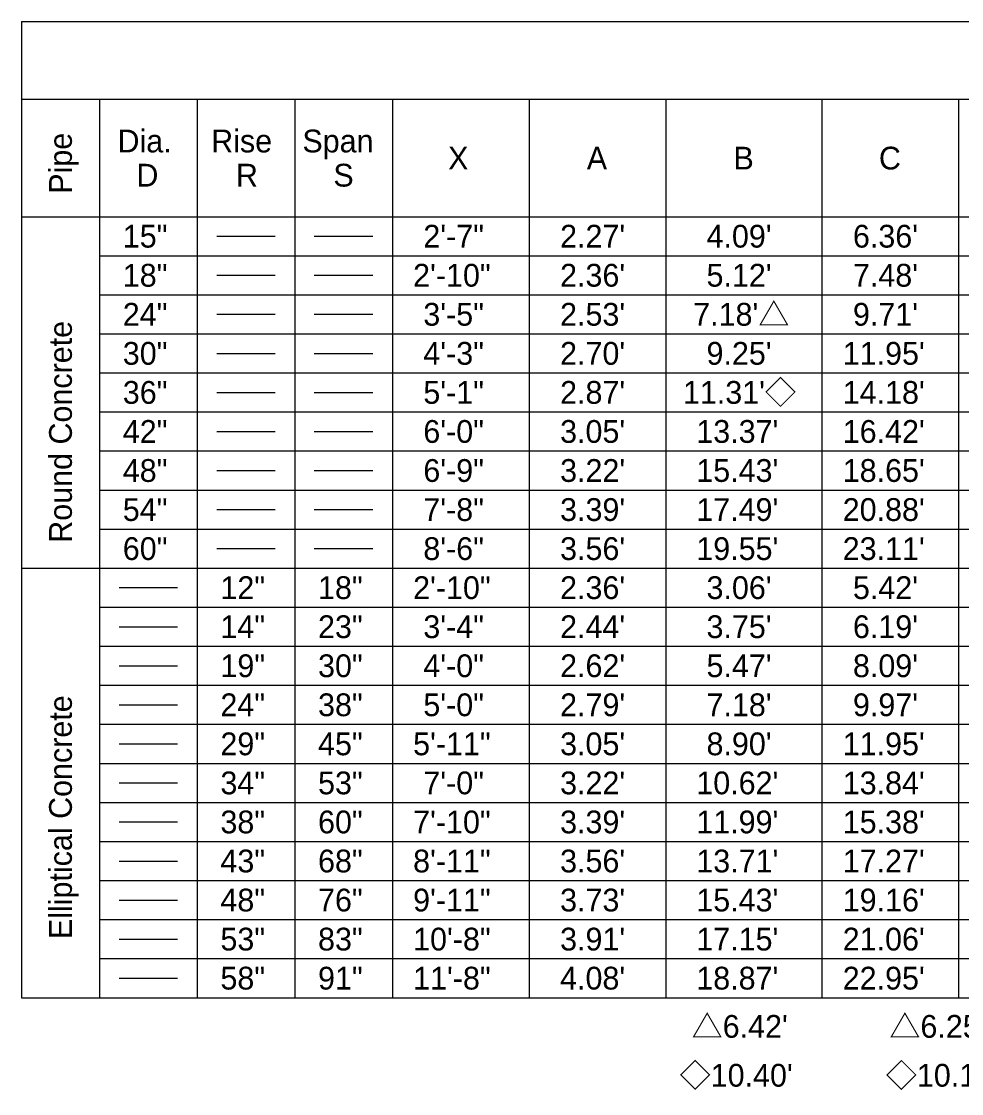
# Model space of a CAD drawing. Extents: x 2 to 14.5, y 0.1 to 8.2.
# Drawn here: x 2 to 4.889, y 4.933 to 8.227 of the extents above; entities that cross this region are included whole.
import ezdxf

# ---------------------------------------------------------------- set-up
doc = ezdxf.new("R2010")
doc.units = 0
doc.layers.add('TextNotes', color=7, linetype='Continuous')
doc.layers.add('TextTables', color=7, linetype='Continuous')

msp = doc.modelspace()

# ---------------------------------------------------------------- linework, layer by layer
at = {"layer": 'TextTables'}
for p, q in [((2, 8.2274), (13.4, 8.2274)), ((2.6, 7.5674), (2.78, 7.5674)), ((2.9, 7.5674), (3.08, 7.5674)), ((2.6, 7.4474), (2.78, 7.4474)), ((2.9, 7.4474), (3.08, 7.4474)), ((2.6, 7.3274), (2.78, 7.3274)), ((2.9, 7.3274), (3.08, 7.3274)), ((2.6, 7.2074), (2.78, 7.2074)), ((2.9, 7.2074), (3.08, 7.2074)), ((2.6, 7.0874), (2.78, 7.0874)), ((2.9, 7.0874), (3.08, 7.0874)), ((2.6, 6.9674), (2.78, 6.9674)), ((2.9, 6.9674), (3.08, 6.9674)), ((2.6, 6.8474), (2.78, 6.8474)), ((2.9, 6.8474), (3.08, 6.8474)), ((2.6, 6.7274), (2.78, 6.7274)), ((2.9, 6.7274), (3.08, 6.7274)), ((2.6, 6.6074), (2.78, 6.6074)), ((2.9, 6.6074), (3.08, 6.6074)), ((2.3, 6.4874), (2.48, 6.4874)), ((2.3, 6.3674), (2.48, 6.3674)), ((2.3, 6.2474), (2.48, 6.2474)), ((2.3, 6.1274), (2.48, 6.1274)), ((2.3, 6.0074), (2.48, 6.0074)), ((2.3, 5.8874), (2.48, 5.8874)), ((2.3, 5.7674), (2.48, 5.7674)), ((2.3, 5.6474), (2.48, 5.6474)), ((2.3, 5.5274), (2.48, 5.5274)), ((2.3, 5.4074), (2.48, 5.4074)), ((2.3, 5.2874), (2.48, 5.2874))]:
    msp.add_line(p, q, dxfattribs=at)
for points in [[(2, 8.2274), (2, 7.9874), (2, 7.6274), (2, 6.5474), (2, 5.2274)], [(13.4, 7.9874), (11.72, 7.9874), (10.04, 7.9874), (8.36, 7.9874), (8, 7.9874), (6.32, 7.9874), (5.96, 7.9874), (5.6, 7.9874), (5.36, 7.9874), (4.88, 7.9874), (4.46, 7.9874), (3.98, 7.9874), (3.56, 7.9874), (3.14, 7.9874), (2.84, 7.9874), (2.54, 7.9874), (2.24, 7.9874), (2, 7.9874)], [(2.24, 7.9874), (2.24, 7.6274), (2.24, 7.5074), (2.24, 7.3874), (2.24, 7.2674), (2.24, 7.1474), (2.24, 7.0274), (2.24, 6.9074), (2.24, 6.7874), (2.24, 6.6674), (2.24, 6.5474), (2.24, 6.4274), (2.24, 6.3074), (2.24, 6.1874), (2.24, 6.0674), (2.24, 5.9474), (2.24, 5.8274), (2.24, 5.7074), (2.24, 5.5874), (2.24, 5.4674), (2.24, 5.3474), (2.24, 5.2274)], [(2.54, 7.9874), (2.54, 7.6274), (2.54, 7.5074), (2.54, 7.3874), (2.54, 7.2674), (2.54, 7.1474), (2.54, 7.0274), (2.54, 6.9074), (2.54, 6.7874), (2.54, 6.6674), (2.54, 6.5474), (2.54, 6.4274), (2.54, 6.3074), (2.54, 6.1874), (2.54, 6.0674), (2.54, 5.9474), (2.54, 5.8274), (2.54, 5.7074), (2.54, 5.5874), (2.54, 5.4674), (2.54, 5.3474), (2.54, 5.2274)], [(2.84, 7.9874), (2.84, 7.6274), (2.84, 7.5074), (2.84, 7.3874), (2.84, 7.2674), (2.84, 7.1474), (2.84, 7.0274), (2.84, 6.9074), (2.84, 6.7874), (2.84, 6.6674), (2.84, 6.5474), (2.84, 6.4274), (2.84, 6.3074), (2.84, 6.1874), (2.84, 6.0674), (2.84, 5.9474), (2.84, 5.8274), (2.84, 5.7074), (2.84, 5.5874), (2.84, 5.4674), (2.84, 5.3474), (2.84, 5.2274)], [(3.14, 7.9874), (3.14, 7.6274), (3.14, 7.5074), (3.14, 7.3874), (3.14, 7.2674), (3.14, 7.1474), (3.14, 7.0274), (3.14, 6.9074), (3.14, 6.7874), (3.14, 6.6674), (3.14, 6.5474), (3.14, 6.4274), (3.14, 6.3074), (3.14, 6.1874), (3.14, 6.0674), (3.14, 5.9474), (3.14, 5.8274), (3.14, 5.7074), (3.14, 5.5874), (3.14, 5.4674), (3.14, 5.3474), (3.14, 5.2274)], [(3.56, 7.9874), (3.56, 7.6274), (3.56, 7.5074), (3.56, 7.3874), (3.56, 7.2674), (3.56, 7.1474), (3.56, 7.0274), (3.56, 6.9074), (3.56, 6.7874), (3.56, 6.6674), (3.56, 6.5474), (3.56, 6.4274), (3.56, 6.3074), (3.56, 6.1874), (3.56, 6.0674), (3.56, 5.9474), (3.56, 5.8274), (3.56, 5.7074), (3.56, 5.5874), (3.56, 5.4674), (3.56, 5.3474), (3.56, 5.2274)], [(3.98, 7.9874), (3.98, 7.6274), (3.98, 7.5074), (3.98, 7.3874), (3.98, 7.2674), (3.98, 7.1474), (3.98, 7.0274), (3.98, 6.9074), (3.98, 6.7874), (3.98, 6.6674), (3.98, 6.5474), (3.98, 6.4274), (3.98, 6.3074), (3.98, 6.1874), (3.98, 6.0674), (3.98, 5.9474), (3.98, 5.8274), (3.98, 5.7074), (3.98, 5.5874), (3.98, 5.4674), (3.98, 5.3474), (3.98, 5.2274)], [(4.46, 7.9874), (4.46, 7.6274), (4.46, 7.5074), (4.46, 7.3874), (4.46, 7.2674), (4.46, 7.1474), (4.46, 7.0274), (4.46, 6.9074), (4.46, 6.7874), (4.46, 6.6674), (4.46, 6.5474), (4.46, 6.4274), (4.46, 6.3074), (4.46, 6.1874), (4.46, 6.0674), (4.46, 5.9474), (4.46, 5.8274), (4.46, 5.7074), (4.46, 5.5874), (4.46, 5.4674), (4.46, 5.3474), (4.46, 5.2274)], [(4.88, 7.9874), (4.88, 7.6274), (4.88, 7.5074), (4.88, 7.3874), (4.88, 7.2674), (4.88, 7.1474), (4.88, 7.0274), (4.88, 6.9074), (4.88, 6.7874), (4.88, 6.6674), (4.88, 6.5474), (4.88, 6.4274), (4.88, 6.3074), (4.88, 6.1874), (4.88, 6.0674), (4.88, 5.9474), (4.88, 5.8274), (4.88, 5.7074), (4.88, 5.5874), (4.88, 5.4674), (4.88, 5.3474), (4.88, 5.2274)], [(2, 7.6274), (2.24, 7.6274), (2.54, 7.6274), (2.84, 7.6274), (3.14, 7.6274), (3.56, 7.6274), (3.98, 7.6274), (4.46, 7.6274), (4.88, 7.6274), (5.36, 7.6274), (5.6, 7.6274), (5.96, 7.6274), (6.32, 7.6274), (6.74, 7.6274), (7.16, 7.6274), (7.58, 7.6274), (8, 7.6274), (8.36, 7.6274)], [(2.24, 7.5074), (2.54, 7.5074), (2.84, 7.5074), (3.14, 7.5074), (3.56, 7.5074), (3.98, 7.5074), (4.46, 7.5074), (4.88, 7.5074), (5.36, 7.5074), (5.6, 7.5074), (5.96, 7.5074), (6.32, 7.5074), (6.74, 7.5074), (7.16, 7.5074), (7.58, 7.5074), (8, 7.5074), (8.36, 7.5074)], [(2.24, 7.3874), (2.54, 7.3874), (2.84, 7.3874), (3.14, 7.3874), (3.56, 7.3874), (3.98, 7.3874), (4.46, 7.3874), (4.88, 7.3874), (5.36, 7.3874), (5.6, 7.3874), (5.96, 7.3874), (6.32, 7.3874), (6.74, 7.3874), (7.16, 7.3874), (7.58, 7.3874), (8, 7.3874), (8.36, 7.3874)], [(2.24, 7.2674), (2.54, 7.2674), (2.84, 7.2674), (3.14, 7.2674), (3.56, 7.2674), (3.98, 7.2674), (4.46, 7.2674), (4.88, 7.2674), (5.36, 7.2674), (5.6, 7.2674), (5.96, 7.2674), (6.32, 7.2674), (6.74, 7.2674), (7.16, 7.2674), (7.58, 7.2674), (8, 7.2674), (8.36, 7.2674)], [(2.24, 7.1474), (2.54, 7.1474), (2.84, 7.1474), (3.14, 7.1474), (3.56, 7.1474), (3.98, 7.1474), (4.46, 7.1474), (4.88, 7.1474), (5.36, 7.1474), (5.6, 7.1474), (5.96, 7.1474), (6.32, 7.1474), (6.74, 7.1474), (7.16, 7.1474), (7.58, 7.1474), (8, 7.1474), (8.36, 7.1474)], [(2.24, 7.0274), (2.54, 7.0274), (2.84, 7.0274), (3.14, 7.0274), (3.56, 7.0274), (3.98, 7.0274), (4.46, 7.0274), (4.88, 7.0274), (5.36, 7.0274), (5.6, 7.0274), (5.96, 7.0274), (6.32, 7.0274), (6.74, 7.0274), (7.16, 7.0274), (7.58, 7.0274), (8, 7.0274), (8.36, 7.0274)], [(2.24, 6.9074), (2.54, 6.9074), (2.84, 6.9074), (3.14, 6.9074), (3.56, 6.9074), (3.98, 6.9074), (4.46, 6.9074), (4.88, 6.9074), (5.36, 6.9074), (5.6, 6.9074), (5.96, 6.9074), (6.32, 6.9074), (6.74, 6.9074), (7.16, 6.9074), (7.58, 6.9074), (8, 6.9074), (8.36, 6.9074)], [(2.24, 6.7874), (2.54, 6.7874), (2.84, 6.7874), (3.14, 6.7874), (3.56, 6.7874), (3.98, 6.7874), (4.46, 6.7874), (4.88, 6.7874), (5.36, 6.7874), (5.6, 6.7874), (5.96, 6.7874), (6.32, 6.7874), (6.74, 6.7874), (7.16, 6.7874), (7.58, 6.7874), (8, 6.7874), (8.36, 6.7874)], [(2.24, 6.6674), (2.54, 6.6674), (2.84, 6.6674), (3.14, 6.6674), (3.56, 6.6674), (3.98, 6.6674), (4.46, 6.6674), (4.88, 6.6674), (5.36, 6.6674), (5.6, 6.6674), (5.96, 6.6674), (6.32, 6.6674), (6.74, 6.6674), (7.16, 6.6674), (7.58, 6.6674), (8, 6.6674), (8.36, 6.6674)], [(2, 6.5474), (2.24, 6.5474), (2.54, 6.5474), (2.84, 6.5474), (3.14, 6.5474), (3.56, 6.5474), (3.98, 6.5474), (4.46, 6.5474), (4.88, 6.5474), (5.36, 6.5474), (5.6, 6.5474), (5.96, 6.5474), (6.32, 6.5474), (6.74, 6.5474), (7.16, 6.5474), (7.58, 6.5474), (8, 6.5474), (8.36, 6.5474)], [(2.24, 6.4274), (2.54, 6.4274), (2.84, 6.4274), (3.14, 6.4274), (3.56, 6.4274), (3.98, 6.4274), (4.46, 6.4274), (4.88, 6.4274), (5.36, 6.4274), (5.6, 6.4274), (5.96, 6.4274), (6.32, 6.4274), (6.74, 6.4274), (7.16, 6.4274), (7.58, 6.4274), (8, 6.4274), (8.36, 6.4274)], [(2.24, 6.3074), (2.54, 6.3074), (2.84, 6.3074), (3.14, 6.3074), (3.56, 6.3074), (3.98, 6.3074), (4.46, 6.3074), (4.88, 6.3074), (5.36, 6.3074), (5.6, 6.3074), (5.96, 6.3074), (6.32, 6.3074), (6.74, 6.3074), (7.16, 6.3074), (7.58, 6.3074), (8, 6.3074), (8.36, 6.3074)], [(2.24, 6.1874), (2.54, 6.1874), (2.84, 6.1874), (3.14, 6.1874), (3.56, 6.1874), (3.98, 6.1874), (4.46, 6.1874), (4.88, 6.1874), (5.36, 6.1874), (5.6, 6.1874), (5.96, 6.1874), (6.32, 6.1874), (6.74, 6.1874), (7.16, 6.1874), (7.58, 6.1874), (8, 6.1874), (8.36, 6.1874)], [(2.24, 6.0674), (2.54, 6.0674), (2.84, 6.0674), (3.14, 6.0674), (3.56, 6.0674), (3.98, 6.0674), (4.46, 6.0674), (4.88, 6.0674), (5.36, 6.0674), (5.6, 6.0674), (5.96, 6.0674), (6.32, 6.0674), (6.74, 6.0674), (7.16, 6.0674), (7.58, 6.0674), (8, 6.0674), (8.36, 6.0674)], [(2.24, 5.9474), (2.54, 5.9474), (2.84, 5.9474), (3.14, 5.9474), (3.56, 5.9474), (3.98, 5.9474), (4.46, 5.9474), (4.88, 5.9474), (5.36, 5.9474), (5.6, 5.9474), (5.96, 5.9474), (6.32, 5.9474), (6.74, 5.9474), (7.16, 5.9474), (7.58, 5.9474), (8, 5.9474), (8.36, 5.9474)], [(2.24, 5.8274), (2.54, 5.8274), (2.84, 5.8274), (3.14, 5.8274), (3.56, 5.8274), (3.98, 5.8274), (4.46, 5.8274), (4.88, 5.8274), (5.36, 5.8274), (5.6, 5.8274), (5.96, 5.8274), (6.32, 5.8274), (6.74, 5.8274), (7.16, 5.8274), (7.58, 5.8274), (8, 5.8274), (8.36, 5.8274)], [(2.24, 5.7074), (2.54, 5.7074), (2.84, 5.7074), (3.14, 5.7074), (3.56, 5.7074), (3.98, 5.7074), (4.46, 5.7074), (4.88, 5.7074), (5.36, 5.7074), (5.6, 5.7074), (5.96, 5.7074), (6.32, 5.7074), (6.74, 5.7074), (7.16, 5.7074), (7.58, 5.7074), (8, 5.7074), (8.36, 5.7074)], [(2.24, 5.5874), (2.54, 5.5874), (2.84, 5.5874), (3.14, 5.5874), (3.56, 5.5874), (3.98, 5.5874), (4.46, 5.5874), (4.88, 5.5874), (5.36, 5.5874), (5.6, 5.5874), (5.96, 5.5874), (6.32, 5.5874), (6.74, 5.5874), (7.16, 5.5874), (7.58, 5.5874), (8, 5.5874), (8.36, 5.5874)], [(2.24, 5.4674), (2.54, 5.4674), (2.84, 5.4674), (3.14, 5.4674), (3.56, 5.4674), (3.98, 5.4674), (4.46, 5.4674), (4.88, 5.4674), (5.36, 5.4674), (5.6, 5.4674), (5.96, 5.4674), (6.32, 5.4674), (6.74, 5.4674), (7.16, 5.4674), (7.58, 5.4674), (8, 5.4674), (8.36, 5.4674)], [(2.24, 5.3474), (2.54, 5.3474), (2.84, 5.3474), (3.14, 5.3474), (3.56, 5.3474), (3.98, 5.3474), (4.46, 5.3474), (4.88, 5.3474), (5.36, 5.3474), (5.6, 5.3474), (5.96, 5.3474), (6.32, 5.3474), (6.74, 5.3474), (7.16, 5.3474), (7.58, 5.3474), (8, 5.3474), (8.36, 5.3474)], [(2, 5.2274), (2.24, 5.2274), (2.54, 5.2274), (2.84, 5.2274), (3.14, 5.2274), (3.56, 5.2274), (3.98, 5.2274), (4.46, 5.2274), (4.88, 5.2274), (5.36, 5.2274), (5.6, 5.2274), (5.96, 5.2274), (6.32, 5.2274), (6.74, 5.2274), (7.16, 5.2274), (7.58, 5.2274), (8, 5.2274), (8.36, 5.2274)]]:
    msp.add_lwpolyline(points, dxfattribs=at)

# ---------------------------------------------------------------- texts
at = {"layer": 'TextNotes'}
for s, rotation, p in [('Pipe', 90, (2.155, 7.6979)), ('15"', 0, (2.3115, 7.5324)), ('2\'-7"', 0, (3.2351, 7.5324)), ("2.27'", 0, (3.6554, 7.5324)), ("4.09'", 0, (4.1054, 7.5324)), ("6.36'", 0, (4.5554, 7.5324)), ('18"', 0, (2.3115, 7.4124)), ('2\'-10"', 0, (3.2037, 7.4124)), ("2.36'", 0, (3.6554, 7.4124)), ("5.12'", 0, (4.1054, 7.4124)), ("7.48'", 0, (4.5554, 7.4124)), ('24"', 0, (2.3115, 7.2924)), ('3\'-5"', 0, (3.2351, 7.2924)), ("2.53'", 0, (3.6554, 7.2924)), ("7.18'△", 0, (4.0645, 7.2924)), ("9.71'", 0, (4.5554, 7.2924)), ('Round Concrete', 90, (2.155, 6.6254)), ('30"', 0, (2.3115, 7.1724)), ('4\'-3"', 0, (3.2351, 7.1724)), ("2.70'", 0, (3.6554, 7.1724)), ("9.25'", 0, (4.1054, 7.1724)), ("11.95'", 0, (4.524, 7.1724)), ('36"', 0, (2.3115, 7.0524)), ('5\'-1"', 0, (3.2351, 7.0524)), ("2.87'", 0, (3.6554, 7.0524)), ("11.31'◇", 0, (4.0329, 7.0524)), ("14.18'", 0, (4.524, 7.0524)), ('42"', 0, (2.3115, 6.9324)), ('6\'-0"', 0, (3.2351, 6.9324)), ("3.05'", 0, (3.6554, 6.9324)), ("13.37'", 0, (4.074, 6.9324)), ("16.42'", 0, (4.524, 6.9324)), ('48"', 0, (2.3115, 6.8124)), ('6\'-9"', 0, (3.2351, 6.8124)), ("3.22'", 0, (3.6554, 6.8124)), ("15.43'", 0, (4.074, 6.8124)), ("18.65'", 0, (4.524, 6.8124)), ('54"', 0, (2.3115, 6.6924)), ('7\'-8"', 0, (3.2351, 6.6924)), ("3.39'", 0, (3.6554, 6.6924)), ("17.49'", 0, (4.074, 6.6924)), ("20.88'", 0, (4.524, 6.6924)), ('60"', 0, (2.3115, 6.5724)), ('8\'-6"', 0, (3.2351, 6.5724)), ("3.56'", 0, (3.6554, 6.5724)), ("19.55'", 0, (4.074, 6.5724)), ("23.11'", 0, (4.524, 6.5724)), ('12"', 0, (2.6115, 6.4524)), ('18"', 0, (2.9115, 6.4524)), ('2\'-10"', 0, (3.2037, 6.4524)), ("2.36'", 0, (3.6554, 6.4524)), ("3.06'", 0, (4.1054, 6.4524)), ("5.42'", 0, (4.5554, 6.4524)), ('14"', 0, (2.6115, 6.3324)), ('23"', 0, (2.9115, 6.3324)), ('3\'-4"', 0, (3.2351, 6.3324)), ("2.44'", 0, (3.6554, 6.3324)), ("3.75'", 0, (4.1054, 6.3324)), ("6.19'", 0, (4.5554, 6.3324)), ('19"', 0, (2.6115, 6.2124)), ('30"', 0, (2.9115, 6.2124)), ('4\'-0"', 0, (3.2351, 6.2124)), ("2.62'", 0, (3.6554, 6.2124)), ("5.47'", 0, (4.1054, 6.2124)), ("8.09'", 0, (4.5554, 6.2124)), ('24"', 0, (2.6115, 6.0924)), ('38"', 0, (2.9115, 6.0924)), ('5\'-0"', 0, (3.2351, 6.0924)), ("2.79'", 0, (3.6554, 6.0924)), ("7.18'", 0, (4.1054, 6.0924)), ("9.97'", 0, (4.5554, 6.0924)), ('Elliptical Concrete', 90, (2.155, 5.4074)), ('29"', 0, (2.6115, 5.9724)), ('45"', 0, (2.9115, 5.9724)), ('5\'-11"', 0, (3.2037, 5.9724)), ("3.05'", 0, (3.6554, 5.9724)), ("8.90'", 0, (4.1054, 5.9724)), ("11.95'", 0, (4.524, 5.9724)), ('34"', 0, (2.6115, 5.8524)), ('53"', 0, (2.9115, 5.8524)), ('7\'-0"', 0, (3.2351, 5.8524)), ("3.22'", 0, (3.6554, 5.8524)), ("10.62'", 0, (4.074, 5.8524)), ("13.84'", 0, (4.524, 5.8524)), ('38"', 0, (2.6115, 5.7324)), ('60"', 0, (2.9115, 5.7324)), ('7\'-10"', 0, (3.2037, 5.7324)), ("3.39'", 0, (3.6554, 5.7324)), ("11.99'", 0, (4.074, 5.7324)), ("15.38'", 0, (4.524, 5.7324)), ('43"', 0, (2.6115, 5.6124)), ('68"', 0, (2.9115, 5.6124)), ('8\'-11"', 0, (3.2037, 5.6124)), ("3.56'", 0, (3.6554, 5.6124)), ("13.71'", 0, (4.074, 5.6124)), ("17.27'", 0, (4.524, 5.6124)), ('48"', 0, (2.6115, 5.4924)), ('76"', 0, (2.9115, 5.4924)), ('9\'-11"', 0, (3.2037, 5.4924)), ("3.73'", 0, (3.6554, 5.4924)), ("15.43'", 0, (4.074, 5.4924)), ("19.16'", 0, (4.524, 5.4924)), ('53"', 0, (2.6115, 5.3724)), ('83"', 0, (2.9115, 5.3724)), ('10\'-8"', 0, (3.2037, 5.3724)), ("3.91'", 0, (3.6554, 5.3724)), ("17.15'", 0, (4.074, 5.3724)), ("21.06'", 0, (4.524, 5.3724)), ('58"', 0, (2.6115, 5.2524)), ('91"', 0, (2.9115, 5.2524)), ('11\'-8"', 0, (3.2037, 5.2524)), ("4.08'", 0, (3.6554, 5.2524)), ("18.87'", 0, (4.074, 5.2524)), ("22.95'", 0, (4.524, 5.2524)), ("△6.42'            △6.25'   Dimensions permitted to allow use of 8' standard pipe lengths.", 0, (4.0597, 5.1042)), ("◇10.40'           ◇10.10'  Dimensions permitted to allow use of 12' standard pipe lengths.", 0, (4.0228, 4.9539))]:
    msp.add_text(s, height=0.07, rotation=rotation, dxfattribs=at).set_placement(p)
for s, p in [('Dia.', (2.2952, 7.8249)), ('Rise', (2.5831, 7.8249)), ('Span', (2.8634, 7.8249)), ('X', (3.3112, 7.7724)), ('A', (3.7375, 7.7724)), ('B', (4.1883, 7.7724)), ('C', (4.6352, 7.7724)), ('D', (2.3534, 7.7199)), ('R', (2.6592, 7.7199)), ('S', (2.9586, 7.7199))]:
    msp.add_text(s, height=0.07, dxfattribs=at).set_placement(p)

doc.saveas('drawing.dxf')
